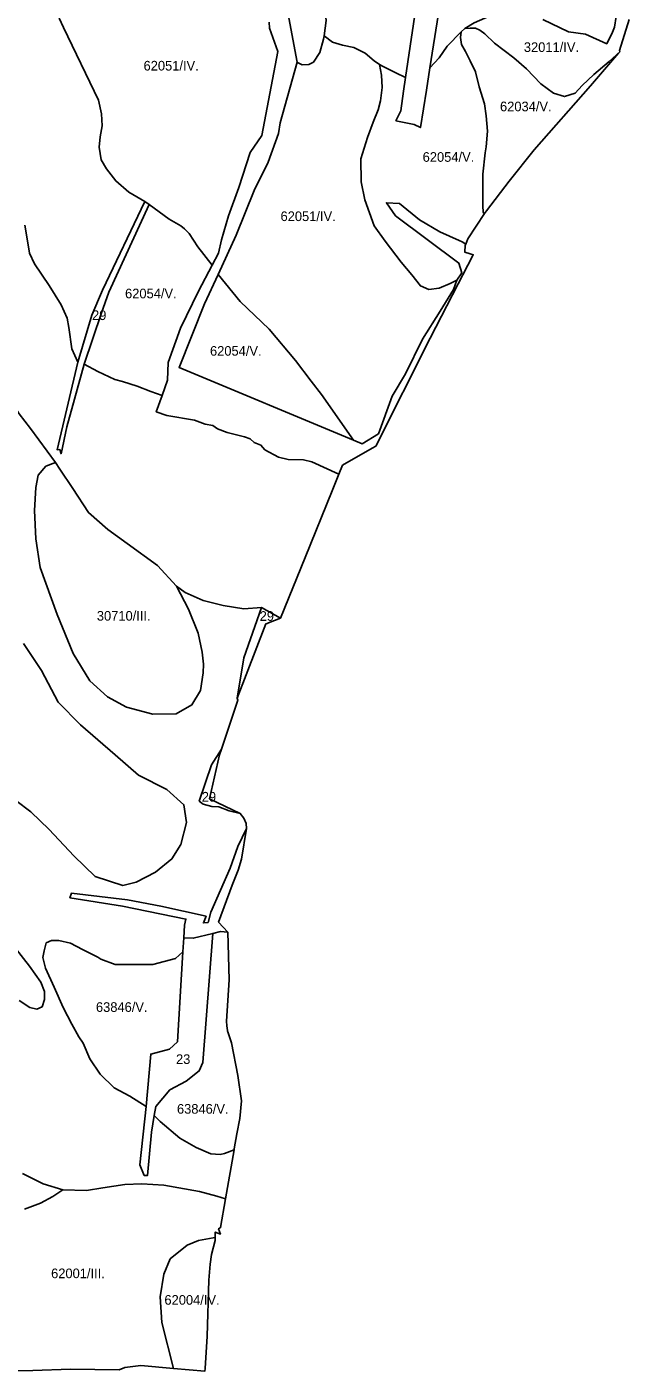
# Model space of a CAD drawing. Extents: x -521621 to -516761, y -1190184 to -1184927.
# Drawn here: x -518423 to -517486, y -1190184 to -1188092 of the extents above; entities that cross this region are included whole.
import ezdxf

# ---------------------------------------------------------------- set-up
doc = ezdxf.new("R2010")
doc.units = 0
doc.layers.add('BPEJ_s', color=7, linetype='Continuous')

msp = doc.modelspace()

# ---------------------------------------------------------------- linework, layer by layer
at = {"layer": 'BPEJ_s'}
for p, q in [((-518179.2, -1189509.3), (-518180.8, -1189531)), ((-518100.9, -1189839.2), (-518114.1, -1189915.8))]:
    msp.add_line(p, q, dxfattribs=at)
for points in [[(-518018.5, -1188061.6), (-518012.5, -1188036.3), (-518000.1, -1188017), (-517983.5, -1188011), (-517972.1, -1188014.7), (-517961.5, -1188041.3), (-517957.4, -1188082.2), (-517960.8, -1188106.3), (-517961.5, -1188111.2), (-517967.5, -1188132.3), (-517977.1, -1188147), (-517984.5, -1188150.7), (-517994.6, -1188151.1), (-518001, -1188147.9), (-518002.8, -1188146.9)], [(-517795.9, -1188156), (-517778.9, -1188047.8), (-517760.3, -1188054.2), (-517726.8, -1188062.7), (-517690.2, -1188069.9), (-517727, -1188086.1), (-517741.8, -1188094.9), (-517747.3, -1188099.8), (-517769.3, -1188122.4), (-517781.4, -1188140.5)], [(-517747.3, -1188099.8), (-517741.8, -1188094.9), (-517733.2, -1188094), (-517725.1, -1188094.4), (-517718.3, -1188097.5), (-517710.7, -1188103), (-517695.5, -1188117.7), (-517665.3, -1188140.3), (-517645.5, -1188157.7), (-517623.3, -1188180.8), (-517603.8, -1188195.2), (-517586.4, -1188200.7), (-517569.7, -1188195.2), (-517559, -1188183.3), (-517541, -1188166.5), (-517517, -1188146.1), (-517500.2, -1188130.8), (-517502.3, -1188133.3), (-517546, -1188183.9), (-517633.8, -1188283.6), (-517672.9, -1188332.2), (-517708, -1188378.3), (-517710.8, -1188382.6), (-517713, -1188381.2), (-517713.5, -1188370.3), (-517713.5, -1188321.6), (-517710.2, -1188288), (-517708.5, -1188278.7), (-517706.4, -1188254.7), (-517708.7, -1188230.5), (-517711.2, -1188211.8), (-517719.1, -1188185.7), (-517725, -1188162.2), (-517733.2, -1188144.8), (-517740.7, -1188130.4), (-517746.7, -1188119.8), (-517748.6, -1188108.8)], [(-518125.7, -1188477.5), (-518097.5, -1188416.5), (-518069.3, -1188347), (-518048, -1188302.7), (-518031.8, -1188257.9), (-518029.2, -1188241.7), (-518002.8, -1188146.9), (-518001, -1188147.9), (-517994.6, -1188151.1), (-517984.5, -1188150.7), (-517977.1, -1188147), (-517967.5, -1188132.3), (-517961.5, -1188111.2), (-517960.8, -1188106.3), (-517947.8, -1188115.9), (-517932, -1188120.4), (-517914.2, -1188124.5), (-517896.7, -1188133.1), (-517882.6, -1188144.8), (-517874.4, -1188150.8), (-517871.6, -1188167.3), (-517870.4, -1188186.7), (-517873, -1188207.3), (-517876.3, -1188221.2), (-517884.3, -1188240.5), (-517892.9, -1188264.5), (-517903.6, -1188297.6), (-517903.1, -1188333.1), (-517897.1, -1188361.5), (-517882.9, -1188401.9), (-517865.9, -1188425.5), (-517840.8, -1188458.2), (-517824.4, -1188477.9), (-517810.8, -1188494.9), (-517797.6, -1188500.9), (-517781.8, -1188498.7), (-517764.7, -1188491.5), (-517754.2, -1188486.4), (-517759.5, -1188500.8), (-517780.3, -1188534.5), (-517807.3, -1188577.8), (-517834.2, -1188632.2), (-517854.6, -1188666.5), (-517876.2, -1188725.1), (-517901.4, -1188741), (-517915.1, -1188735.4), (-517964.6, -1188664.2), (-517980.6, -1188643.5), (-518005.2, -1188611.3), (-518046.2, -1188562.6), (-518091.5, -1188519.5)], [(-517874.4, -1188150.8), (-517869.9, -1188153.4), (-517849.1, -1188163.9), (-517833.9, -1188171.1), (-517837, -1188192.2), (-517841.1, -1188222.6), (-517849, -1188238.3), (-517820.5, -1188244), (-517810.8, -1188248.8), (-517801.4, -1188190.7), (-517795.9, -1188156), (-517781.4, -1188140.5), (-517769.3, -1188122.4), (-517747.3, -1188099.8), (-517748.6, -1188108.8), (-517746.7, -1188119.8), (-517740.7, -1188130.4), (-517733.2, -1188144.8), (-517725, -1188162.2), (-517719.1, -1188185.7), (-517711.2, -1188211.8), (-517708.7, -1188230.5), (-517706.4, -1188254.7), (-517708.5, -1188278.7), (-517710.2, -1188288), (-517713.5, -1188321.6), (-517713.5, -1188370.3), (-517713, -1188381.2), (-517710.8, -1188382.6), (-517736.9, -1188422.2), (-517740.3, -1188430.3), (-517746, -1188426.6), (-517750.6, -1188424.3), (-517780.5, -1188411.3), (-517812.1, -1188392.5), (-517843.1, -1188366.9), (-517863.7, -1188365.7), (-517849.4, -1188386), (-517751, -1188459.7), (-517746.4, -1188474.9), (-517754.2, -1188486.4), (-517764.7, -1188491.5), (-517781.8, -1188498.7), (-517797.6, -1188500.9), (-517810.8, -1188494.9), (-517824.4, -1188477.9), (-517840.8, -1188458.2), (-517865.9, -1188425.5), (-517882.9, -1188401.9), (-517897.1, -1188361.5), (-517903.1, -1188333.1), (-517903.6, -1188297.6), (-517892.9, -1188264.5), (-517884.3, -1188240.5), (-517876.3, -1188221.2), (-517873, -1188207.3), (-517870.4, -1188186.7), (-517871.6, -1188167.3)], [(-518343.9, -1188613.8), (-518322.4, -1188540.8), (-518305.5, -1188501.9), (-518239.5, -1188363.9), (-518233, -1188368.7), (-518295.7, -1188504.7), (-518307.3, -1188537.1), (-518334.1, -1188616.7), (-518349.4, -1188671.3), (-518361.1, -1188714.5), (-518370.2, -1188756.4), (-518372.1, -1188749.8), (-518376.4, -1188750.2)], [(-518334.1, -1188616.7), (-518307.3, -1188537.1), (-518295.7, -1188504.7), (-518233, -1188368.7), (-518201.9, -1188391.3), (-518183.8, -1188401.6), (-518177.8, -1188406.3), (-518170.7, -1188413.4), (-518157, -1188434.2), (-518134.7, -1188462.8), (-518156.1, -1188503.3), (-518184, -1188560.9), (-518203.2, -1188614.4), (-518204.6, -1188641.8), (-518213, -1188665.8), (-518230.4, -1188659.7), (-518251.7, -1188651.4), (-518274.3, -1188643.7), (-518286.2, -1188640.6), (-518313.1, -1188628.3)], [(-518125.7, -1188477.5), (-518091.5, -1188519.5), (-518046.2, -1188562.6), (-518005.2, -1188611.3), (-517980.6, -1188643.5), (-517964.6, -1188664.2), (-517915.1, -1188735.4), (-518186.5, -1188622.3), (-518146.7, -1188522.9)], [(-518378.9, -1188770), (-518371.8, -1188780.5), (-518351.8, -1188810.5), (-518327.2, -1188847.8), (-518297.2, -1188874.1), (-518267.3, -1188896.1), (-518220, -1188930.3), (-518190.6, -1188962.4), (-518171.7, -1188998.1), (-518156.5, -1189035.4), (-518150.7, -1189064.8), (-518148.5, -1189083.8), (-518149.1, -1189097.2), (-518153.1, -1189124.5), (-518166.5, -1189147.2), (-518190.9, -1189161.2), (-518227.5, -1189161.7), (-518268.2, -1189150.7), (-518297.8, -1189134.4), (-518325.1, -1189109.4), (-518351.3, -1189067), (-518376.3, -1189006.5), (-518402.4, -1188933.2), (-518409.4, -1188888.5), (-518411.4, -1188844.4), (-518409.4, -1188808.9), (-518405.6, -1188789.8), (-518393.7, -1188775.5)], [(-518096, -1189136.7), (-518085.6, -1189073.8), (-518058.2, -1188995.6), (-518028.7, -1189012), (-518037.9, -1189015.7), (-518047.1, -1189019.4), (-518049.3, -1189020.3), (-518051.5, -1189021.2)], [(-518120.4, -1189216), (-518135.9, -1189240.1), (-518155.1, -1189296.8), (-518148.9, -1189301.3), (-518135.5, -1189305.4), (-518124.3, -1189305.7), (-518108.2, -1189311.8), (-518091.3, -1189315.9), (-518139, -1189293.4), (-518123.3, -1189224.6)], [(-518179.2, -1189509.3), (-518178, -1189490), (-518175.8, -1189480.2), (-518274.5, -1189460.2), (-518356.4, -1189447.2), (-518354.1, -1189440), (-518266.9, -1189450.3), (-518214.9, -1189460.3), (-518144.4, -1189476), (-518148.6, -1189486.3), (-518141.3, -1189485.4), (-518136.9, -1189469.8), (-518107, -1189401.2), (-518094.8, -1189367.3), (-518081.7, -1189339.3), (-518089.2, -1189386.9), (-518094.2, -1189404.4), (-518103.7, -1189427.7), (-518125, -1189484.9), (-518110.3, -1189500.7), (-518121.9, -1189499.5), (-518133.9, -1189502.5), (-518164.3, -1189510)], [(-518225, -1189786), (-518222.6, -1189772), (-518200.6, -1189745.9), (-518175.6, -1189732.3), (-518155.1, -1189716.5), (-518149.2, -1189703.3), (-518133.9, -1189502.5), (-518121.9, -1189499.5), (-518110.3, -1189500.7), (-518108.4, -1189574.9), (-518112.6, -1189639.2), (-518111.9, -1189646.4), (-518111.3, -1189653.6), (-518111, -1189654.6), (-518110.6, -1189655.5), (-518104.7, -1189672.7), (-518094.8, -1189723.5), (-518089.5, -1189762.9), (-518092, -1189790.8), (-518096.3, -1189814.2), (-518100.6, -1189837.6), (-518100.9, -1189839.2), (-518115.7, -1189845.2), (-518122.6, -1189846.5), (-518137.2, -1189845.5), (-518159.6, -1189835.9), (-518185.3, -1189821.4), (-518215.7, -1189795)], [(-518237.6, -1189771.7), (-518263.2, -1189755.9), (-518287.5, -1189742.6), (-518309.5, -1189721.8), (-518325.1, -1189697.8), (-518335.7, -1189673.5), (-518342.4, -1189663.4), (-518353.3, -1189643.6), (-518366.6, -1189617.8), (-518380.7, -1189586.4), (-518394.4, -1189556.9), (-518398.4, -1189540), (-518396.4, -1189529.5), (-518393.2, -1189517.4), (-518385.1, -1189513.4), (-518373.8, -1189513.4), (-518355.3, -1189517.8), (-518336.8, -1189527.5), (-518312.9, -1189539.8), (-518308.4, -1189542.8), (-518286, -1189550.8), (-518260.5, -1189551.2), (-518227.5, -1189551.2), (-518191.8, -1189541.7), (-518180.8, -1189531), (-518188.9, -1189671.5), (-518201.4, -1189682.9), (-518230.5, -1189690.3)], [(-518237.6, -1189771.7), (-518230.5, -1189690.3), (-518201.4, -1189682.9), (-518188.9, -1189671.5), (-518180.8, -1189531), (-518179.2, -1189509.3), (-518164.3, -1189510), (-518133.9, -1189502.5), (-518149.2, -1189703.3), (-518155.1, -1189716.5), (-518175.6, -1189732.3), (-518200.6, -1189745.9), (-518222.6, -1189772), (-518225, -1189786), (-518229.3, -1189811.7), (-518235.5, -1189879), (-518240.7, -1189879), (-518247.6, -1189862.8)], [(-518195.1, -1190179.3), (-518213.5, -1190108), (-518216, -1190068), (-518210, -1190032.5), (-518200.5, -1190009), (-518174, -1189987.5), (-518156, -1189980.5), (-518133.2, -1189976), (-518130.3, -1189975.5), (-518130.4, -1189980.4), (-518136, -1190002.1), (-518137.8, -1190017.1), (-518140.2, -1190042.2), (-518142.7, -1190129.2), (-518145.9, -1190179.6), (-518146.2, -1190183.6)]]:
    msp.add_lwpolyline(points, close=True, dxfattribs=at)
for points in [[(-517814.3, -1188038.1), (-517833.9, -1188171.1), (-517849.1, -1188163.9), (-517869.9, -1188153.4), (-517874.4, -1188150.8), (-517882.6, -1188144.8), (-517896.7, -1188133.1), (-517914.2, -1188124.5), (-517932, -1188120.4), (-517947.8, -1188115.9), (-517960.8, -1188106.3), (-517957.4, -1188082.2)], [(-517778.9, -1188047.8), (-517795.9, -1188156), (-517801.4, -1188190.7), (-517810.8, -1188248.8), (-517820.5, -1188244), (-517849, -1188238.3), (-517841.1, -1188222.6), (-517837, -1188192.2), (-517833.9, -1188171.1), (-517814.3, -1188038.1)], [(-518373.3, -1188078.6), (-518366.5, -1188093.4), (-518311.8, -1188206.4), (-518307, -1188227.7), (-518306, -1188245.9), (-518309.4, -1188263.1), (-518310.9, -1188279.3), (-518307.5, -1188298.9), (-518299.6, -1188313.2), (-518284.9, -1188331.8), (-518264.8, -1188349.5), (-518239.5, -1188363.9), (-518305.5, -1188501.9), (-518322.4, -1188540.8), (-518343.9, -1188613.8), (-518353.2, -1188593.3), (-518357.9, -1188560), (-518360.7, -1188545.3), (-518369.8, -1188524.7), (-518388.5, -1188494.6), (-518411.5, -1188460.8), (-518419, -1188444.2), (-518422.2, -1188425.1), (-518426.5, -1188400.9)], [(-518046.2, -1188085.1), (-518045.9, -1188094), (-518032.9, -1188130.7), (-518057.5, -1188261.2), (-518075.9, -1188287.7), (-518093.5, -1188342.1), (-518109.3, -1188386.2), (-518120.5, -1188423.4), (-518124.9, -1188444.3), (-518134.7, -1188462.8), (-518157, -1188434.2), (-518170.7, -1188413.4), (-518177.8, -1188406.3), (-518183.8, -1188401.6), (-518201.9, -1188391.3), (-518233, -1188368.7), (-518239.5, -1188363.9), (-518264.8, -1188349.5), (-518284.9, -1188331.8), (-518299.6, -1188313.2), (-518307.5, -1188298.9), (-518310.9, -1188279.3), (-518309.4, -1188263.1), (-518306, -1188245.9), (-518307, -1188227.7), (-518311.8, -1188206.4), (-518366.5, -1188093.4), (-518373.3, -1188078.6)], [(-518018.5, -1188061.6), (-518002.8, -1188146.9), (-518029.2, -1188241.7), (-518031.8, -1188257.9), (-518048, -1188302.7), (-518069.3, -1188347), (-518097.5, -1188416.5), (-518125.7, -1188477.5), (-518146.7, -1188522.9), (-518186.5, -1188622.3), (-517915.1, -1188735.4), (-517901.4, -1188741), (-517876.2, -1188725.1), (-517854.6, -1188666.5), (-517834.2, -1188632.2), (-517807.3, -1188577.8), (-517780.3, -1188534.5), (-517759.5, -1188500.8), (-517754.2, -1188486.4), (-517746.4, -1188474.9), (-517751, -1188459.7), (-517849.4, -1188386), (-517863.7, -1188365.7), (-517843.1, -1188366.9), (-517812.1, -1188392.5), (-517780.5, -1188411.3), (-517750.6, -1188424.3), (-517746, -1188426.6), (-517740.3, -1188430.3), (-517741, -1188431.9), (-517741.8, -1188442.6), (-517733.2, -1188445.2), (-517728.5, -1188446.6), (-517729.8, -1188449.1), (-517751.8, -1188491.8), (-517795.4, -1188576.6), (-517880.1, -1188744.4), (-517885.7, -1188747.6), (-517931.9, -1188774.1), (-517937.6, -1188788.1), (-517979.6, -1188768.8), (-517992.7, -1188766), (-518016.6, -1188765.4), (-518031.5, -1188761.5), (-518052.8, -1188750.2), (-518059.1, -1188743.1), (-518069.3, -1188739), (-518075.8, -1188733.3), (-518084.5, -1188729.8), (-518111.7, -1188723.1), (-518126.5, -1188717.4), (-518134, -1188712.4), (-518145.7, -1188710.4), (-518162.6, -1188703.9), (-518205.7, -1188696.7), (-518221.9, -1188691), (-518213, -1188665.8), (-518204.6, -1188641.8), (-518203.2, -1188614.4), (-518184, -1188560.9), (-518156.1, -1188503.3), (-518134.7, -1188462.8), (-518124.9, -1188444.3), (-518120.5, -1188423.4), (-518109.3, -1188386.2), (-518093.5, -1188342.1), (-518075.9, -1188287.7), (-518057.5, -1188261.2), (-518032.9, -1188130.7), (-518045.9, -1188094), (-518046.2, -1188085.1)], [(-517620.5, -1188080.6), (-517580.5, -1188100.1), (-517553.7, -1188103.6), (-517520.8, -1188118.4), (-517512, -1188100.4), (-517508.8, -1188092.7), (-517506.3, -1188075.8)], [(-517506.3, -1188075.8), (-517508.8, -1188092.7), (-517512, -1188100.4), (-517520.8, -1188118.4), (-517553.7, -1188103.6), (-517580.5, -1188100.1), (-517620.5, -1188080.6)], [(-517485.9, -1188080.7), (-517500.7, -1188128.8), (-517500.2, -1188130.8), (-517517, -1188146.1), (-517541, -1188166.5), (-517559, -1188183.3), (-517569.7, -1188195.2), (-517586.4, -1188200.7), (-517603.8, -1188195.2), (-517623.3, -1188180.8), (-517645.5, -1188157.7), (-517665.3, -1188140.3), (-517695.5, -1188117.7), (-517710.7, -1188103), (-517718.3, -1188097.5), (-517725.1, -1188094.4), (-517733.2, -1188094), (-517741.8, -1188094.9), (-517727, -1188086.1)], [(-518426.5, -1188400.9), (-518422.2, -1188425.1), (-518419, -1188444.2), (-518411.5, -1188460.8), (-518388.5, -1188494.6), (-518369.8, -1188524.7), (-518360.7, -1188545.3), (-518357.9, -1188560), (-518353.2, -1188593.3), (-518343.9, -1188613.8), (-518376.4, -1188750.2), (-518372.1, -1188749.8), (-518370.2, -1188756.4), (-518361.1, -1188714.5), (-518349.4, -1188671.3), (-518334.1, -1188616.7), (-518313.1, -1188628.3), (-518286.2, -1188640.6), (-518274.3, -1188643.7), (-518251.7, -1188651.4), (-518230.4, -1188659.7), (-518213, -1188665.8), (-518221.9, -1188691), (-518205.7, -1188696.7), (-518162.6, -1188703.9), (-518145.7, -1188710.4), (-518134, -1188712.4), (-518126.5, -1188717.4), (-518111.7, -1188723.1), (-518084.5, -1188729.8), (-518075.8, -1188733.3), (-518069.3, -1188739), (-518059.1, -1188743.1), (-518052.8, -1188750.2), (-518031.5, -1188761.5), (-518016.6, -1188765.4), (-517992.7, -1188766), (-517979.6, -1188768.8), (-517937.6, -1188788.1), (-517947.9, -1188813.9), (-517990.3, -1188917.8), (-518028.7, -1189012), (-518058.2, -1188995.6), (-518085.6, -1188997.6), (-518117.6, -1188992.3), (-518149.1, -1188984.9), (-518177, -1188972.3), (-518190.6, -1188962.4), (-518220, -1188930.3), (-518267.3, -1188896.1), (-518297.2, -1188874.1), (-518327.2, -1188847.8), (-518351.8, -1188810.5), (-518371.8, -1188780.5), (-518378.9, -1188770), (-518417.8, -1188716.8), (-518435.5, -1188694.4)], [(-518480.4, -1188633), (-518467.4, -1188644.9), (-518453.9, -1188663.6), (-518442.8, -1188683), (-518435.5, -1188694.4), (-518417.8, -1188716.8), (-518378.9, -1188770)], [(-518378.9, -1188770), (-518393.7, -1188775.5), (-518405.6, -1188789.8), (-518409.4, -1188808.9), (-518411.4, -1188844.4), (-518409.4, -1188888.5), (-518402.4, -1188933.2), (-518376.3, -1189006.5), (-518351.3, -1189067), (-518325.1, -1189109.4), (-518297.8, -1189134.4), (-518268.2, -1189150.7), (-518227.5, -1189161.7), (-518190.9, -1189161.2), (-518166.5, -1189147.2), (-518153.1, -1189124.5), (-518149.1, -1189097.2), (-518148.5, -1189083.8), (-518150.7, -1189064.8), (-518156.5, -1189035.4), (-518171.7, -1188998.1), (-518190.6, -1188962.4)], [(-518190.6, -1188962.4), (-518177, -1188972.3), (-518149.1, -1188984.9), (-518117.6, -1188992.3), (-518085.6, -1188997.6), (-518058.2, -1188995.6)], [(-518058.2, -1188995.6), (-518085.6, -1189073.8), (-518096, -1189136.7)], [(-518428.8, -1189051.4), (-518400.3, -1189093.6), (-518374.8, -1189142.6), (-518339.6, -1189177.9), (-518285.7, -1189225), (-518249.4, -1189256.4), (-518205.3, -1189278.9), (-518178.8, -1189302.5), (-518174.9, -1189329.9), (-518183.7, -1189364.3), (-518197.5, -1189386.8), (-518222.9, -1189407.4), (-518253.3, -1189423.1), (-518273.9, -1189428), (-518317, -1189414.3), (-518350.3, -1189381.9), (-518388.6, -1189340.7), (-518417, -1189313.3), (-518464, -1189278)], [(-518464, -1189278), (-518417, -1189313.3), (-518388.6, -1189340.7), (-518350.3, -1189381.9), (-518317, -1189414.3), (-518273.9, -1189428), (-518253.3, -1189423.1), (-518222.9, -1189407.4), (-518197.5, -1189386.8), (-518183.7, -1189364.3), (-518174.9, -1189329.9), (-518178.8, -1189302.5), (-518205.3, -1189278.9), (-518249.4, -1189256.4), (-518285.7, -1189225), (-518339.6, -1189177.9), (-518374.8, -1189142.6), (-518400.3, -1189093.6), (-518428.8, -1189051.4)], [(-518096, -1189136.7), (-518094.8, -1189139.9), (-518120.4, -1189216)], [(-518120.4, -1189216), (-518135.9, -1189240.1), (-518155.1, -1189296.8), (-518148.9, -1189301.3), (-518135.5, -1189305.4), (-518124.3, -1189305.7), (-518108.2, -1189311.8), (-518091.3, -1189315.9), (-518085.8, -1189323.2)], [(-518085.8, -1189323.2), (-518081.9, -1189331.6), (-518081.7, -1189339.3)], [(-518081.7, -1189339.3), (-518094.8, -1189367.3), (-518107, -1189401.2), (-518136.9, -1189469.8), (-518141.3, -1189485.4), (-518148.6, -1189486.3), (-518144.4, -1189476), (-518214.9, -1189460.3), (-518266.9, -1189450.3), (-518354.1, -1189440), (-518356.4, -1189447.2), (-518274.5, -1189460.2), (-518175.8, -1189480.2), (-518178, -1189490), (-518179.2, -1189509.3)], [(-518180.8, -1189531), (-518191.8, -1189541.7), (-518227.5, -1189551.2), (-518260.5, -1189551.2), (-518286, -1189550.8), (-518308.4, -1189542.8), (-518312.9, -1189539.8), (-518336.8, -1189527.5), (-518355.3, -1189517.8), (-518373.8, -1189513.4), (-518385.1, -1189513.4), (-518393.2, -1189517.4), (-518396.4, -1189529.5), (-518398.4, -1189540), (-518394.4, -1189556.9), (-518380.7, -1189586.4), (-518366.6, -1189617.8), (-518353.3, -1189643.6), (-518342.4, -1189663.4), (-518335.7, -1189673.5), (-518325.1, -1189697.8), (-518309.5, -1189721.8), (-518287.5, -1189742.6), (-518263.2, -1189755.9), (-518237.6, -1189771.7)], [(-518441.5, -1189525.1), (-518419.4, -1189553.3), (-518401.6, -1189578.7), (-518396, -1189592.8), (-518396, -1189605.3), (-518399.6, -1189616.6), (-518407.7, -1189620.6), (-518418.5, -1189617.8), (-518435.1, -1189606.9)], [(-518435.1, -1189606.9), (-518418.5, -1189617.8), (-518407.7, -1189620.6), (-518399.6, -1189616.6), (-518396, -1189605.3), (-518396, -1189592.8), (-518401.6, -1189578.7), (-518419.4, -1189553.3), (-518441.5, -1189525.1)], [(-518237.6, -1189771.7), (-518247.6, -1189862.8), (-518240.7, -1189879), (-518235.5, -1189879), (-518229.3, -1189811.7), (-518225, -1189786)], [(-518225, -1189786), (-518215.7, -1189795), (-518185.3, -1189821.4), (-518159.6, -1189835.9), (-518137.2, -1189845.5), (-518122.6, -1189846.5), (-518115.7, -1189845.2), (-518100.9, -1189839.2)], [(-518430.3, -1189875.9), (-518397.7, -1189892.2), (-518367.3, -1189901.6), (-518383.1, -1189911.9), (-518402, -1189922.2), (-518426.9, -1189931.6)], [(-518367.3, -1189901.6), (-518397.7, -1189892.2), (-518430.3, -1189875.9)], [(-518426.9, -1189931.6), (-518402, -1189922.2), (-518383.1, -1189911.9), (-518367.3, -1189901.6), (-518330.4, -1189902.5), (-518305.1, -1189898.6), (-518270.8, -1189893.5), (-518244.2, -1189892.2), (-518210.1, -1189894.4), (-518154.7, -1189904.3), (-518127.9, -1189911.5), (-518114.1, -1189915.8), (-518121.8, -1189960.4), (-518125, -1189962.2), (-518122, -1189970.3), (-518130.2, -1189967.2), (-518130.3, -1189975.5), (-518133.2, -1189976), (-518156, -1189980.5), (-518174, -1189987.5), (-518200.5, -1190009), (-518210, -1190032.5), (-518216, -1190068), (-518213.5, -1190108), (-518195.1, -1190179.3), (-518245.7, -1190174.9), (-518270.6, -1190177.8), (-518279.5, -1190181.4), (-518355.3, -1190180.4), (-518414.2, -1190182.6), (-518442.7, -1190183.2)], [(-518114.1, -1189915.8), (-518127.9, -1189911.5), (-518154.7, -1189904.3), (-518210.1, -1189894.4), (-518244.2, -1189892.2), (-518270.8, -1189893.5), (-518305.1, -1189898.6), (-518330.4, -1189902.5), (-518367.3, -1189901.6)]]:
    msp.add_lwpolyline(points, dxfattribs=at)

# ---------------------------------------------------------------- texts
for s, height, p in [('32011/IV.', 15, (-517649.8, -1188131.2)), ('62051/IV.', 15, (-518241.7, -1188160.1)), ('62034/V.', 15, (-517686.9, -1188223.5)), ('62054/V.', 15, (-517807.3, -1188302.1)), ('62051/IV.', 15, (-518028.5, -1188394.3)), ('62054/V.', 15, (-518270.5, -1188514.5)), ('29', 15, (-518321.9, -1188548.3)), ('62054/V.', 15, (-518138.3, -1188603.8)), ('30710/III.', 15, (-518314.4, -1189016)), ('29', 15, (-518061, -1189016.3)), ('29', 15, (-518151.1, -1189297.5)), ('29', 0.0647, (-518263, -1189457.1)), ('63846/V.', 15, (-518315.8, -1189624.7)), ('23', 15, (-518191.2, -1189705.7)), ('63846/V.', 15, (-518189.7, -1189783.1)), ('62001/III.', 15, (-518385.6, -1190039)), ('62004/IV.', 15, (-518209.2, -1190080.3))]:
    msp.add_text(s, height=height, dxfattribs=at).set_placement(p)

doc.saveas('drawing.dxf')
